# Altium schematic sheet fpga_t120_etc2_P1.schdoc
size 839 x 594 mm; Symbol: Drawing-Symbol_A4; @Project Name: FPGA_motors_V3_0_4; @Page Count: 1; @Update Date: 2025-12-23; @Create Date: 2025-12-23; @Schematic Name: fpga_t120_etc2; @Page No: 1; @Page Name: P1; Company: EasyEDA.com; Version: V1.0; Page Size: A4; @Create Time: 13:22:03; @Update Time: 14:22:09; Border: 1; Width: 3304; Height: 2338; Region Start: 1; X Region Count: 6; Y Region Count: 4; Blade Width: 10; Title Block Position: 3; Device: Drawing-Symbol_A4
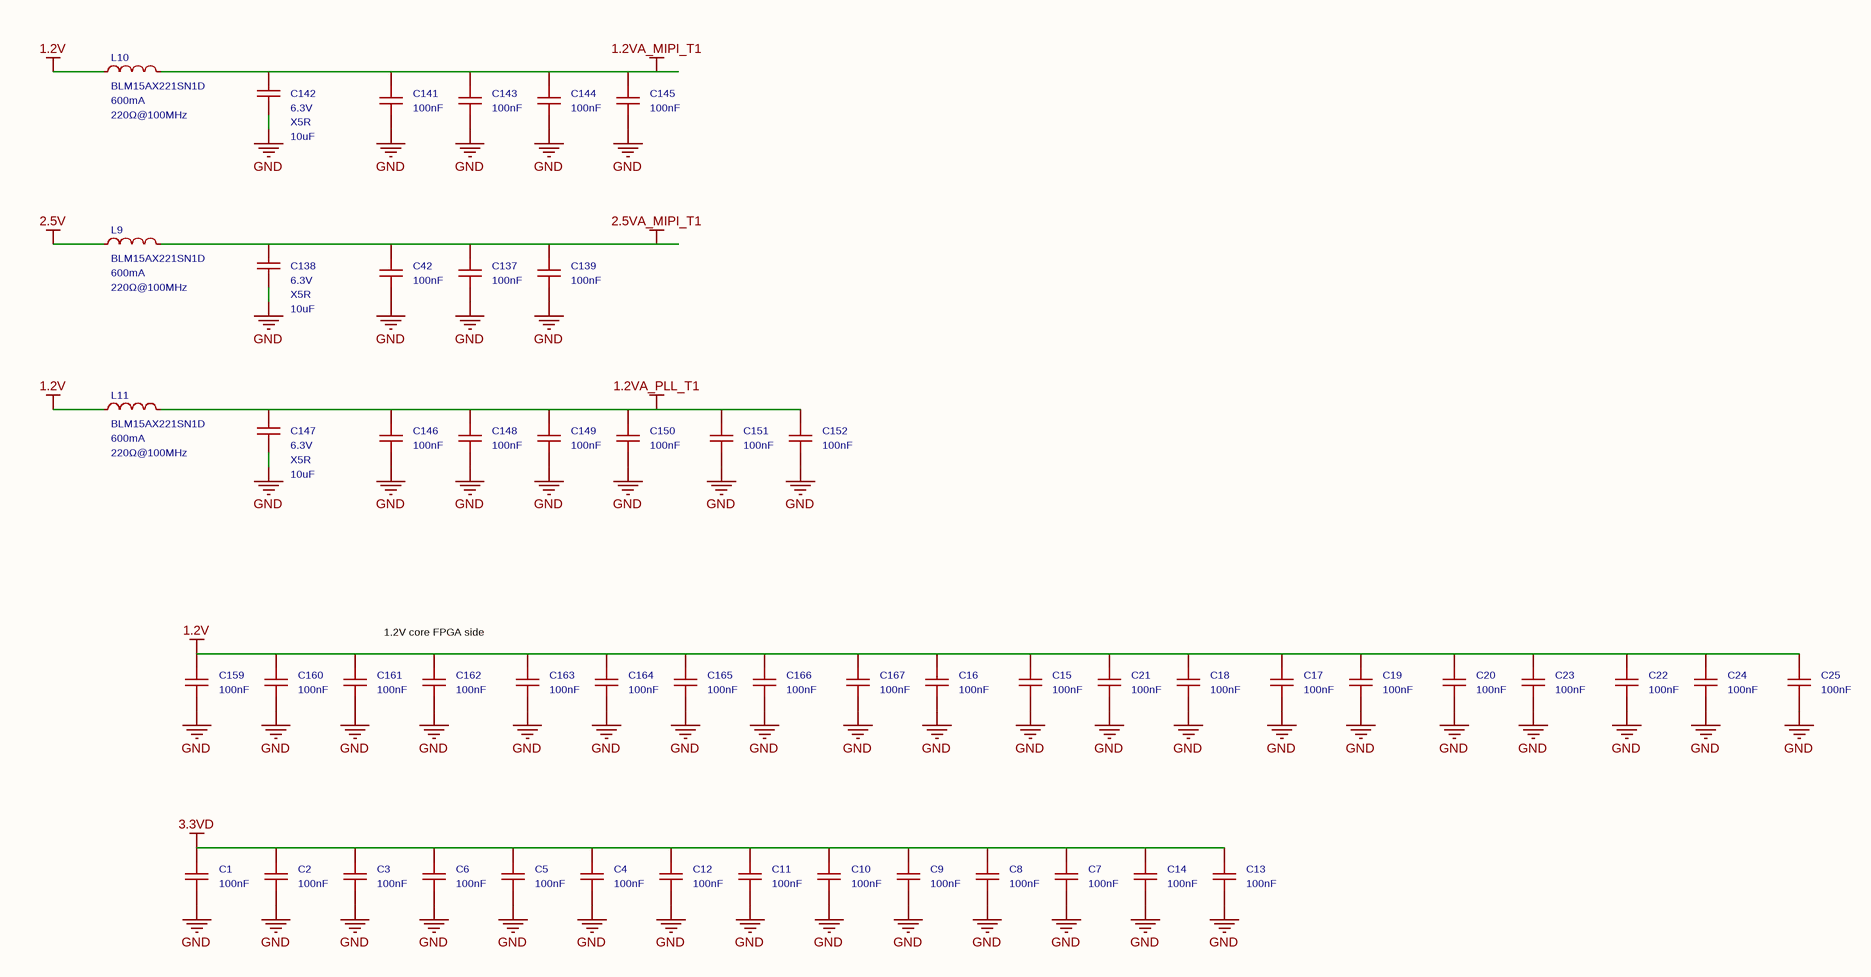
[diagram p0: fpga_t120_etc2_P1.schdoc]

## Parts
C1  100nF  [C0201]
C2  100nF  [C0201]
C3  100nF  [C0201]
C4  100nF  [C0201]
C5  100nF  [C0201]
C6  100nF  [C0201]
C7  100nF  [C0201]
C8  100nF  [C0201]
C9  100nF  [C0201]
C10  100nF  [C0201]
C11  100nF  [C0201]
C12  100nF  [C0201]
C13  100nF  [C0201]
C14  100nF  [C0201]
C15  100nF  [C0201]
C16  100nF  [C0201]
C17  100nF  [C0201]
C18  100nF  [C0201]
C19  100nF  [C0201]
C20  100nF  [C0201]
C21  100nF  [C0201]
C22  100nF  [C0201]
C23  100nF  [C0201]
C24  100nF  [C0201]
C25  100nF  [C0201]
C42  100nF  [C0201]
C137  100nF  [C0201]
C138  10uF  Voltage Rating: 6.3V  Temperature Coefficient: X5R  [C0402]
C139  100nF  [C0201]
C141  100nF  [C0201]
C142  10uF  Voltage Rating: 6.3V  Temperature Coefficient: X5R  [C0402]
C143  100nF  [C0201]
C144  100nF  [C0201]
C145  100nF  [C0201]
C146  100nF  [C0201]
C147  10uF  Voltage Rating: 6.3V  Temperature Coefficient: X5R  [C0402]
C148  100nF  [C0201]
C149  100nF  [C0201]
C150  100nF  [C0201]
C151  100nF  [C0201]
C152  100nF  [C0201]
C159  100nF  [C0201]
C160  100nF  [C0201]
C161  100nF  [C0201]
C162  100nF  [C0201]
C163  100nF  [C0201]
C164  100nF  [C0201]
C165  100nF  [C0201]
C166  100nF  [C0201]
C167  100nF  [C0201]
L9  BLM15AX221SN1D  Impedance @ Frequency: 220Ω@100MHz  Current Rating: 600mA  [L0402]
L10  BLM15AX221SN1D  Impedance @ Frequency: 220Ω@100MHz  Current Rating: 600mA  [L0402]
L11  BLM15AX221SN1D  Impedance @ Frequency: 220Ω@100MHz  Current Rating: 600mA  [L0402]

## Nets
1.2V: C15.1 C16.1 C17.1 C18.1 C19.1 C20.1 C21.1 C22.1 C23.1 C24.1 C25.1 C159.1 C160.1 C161.1 C162.1 C163.1 C164.1 C165.1 C166.1 C167.1 L10.1 L11.1
1.2VA_MIPI_T1: C141.1 C142.2 C143.1 C144.1 C145.1 L10.2
1.2VA_PLL_T1: C146.1 C147.2 C148.1 C149.1 C150.1 C151.1 C152.1 L11.2
2.5V: L9.1
2.5VA_MIPI_T1: C42.1 C137.1 C138.2 C139.1 L9.2
3.3VD: C1.2 C2.2 C3.2 C4.2 C5.2 C6.2 C7.2 C8.2 C9.2 C10.2 C11.2 C12.2 C13.2 C14.2
GND: C1.1 C2.1 C3.1 C4.1 C5.1 C6.1 C7.1 C8.1 C9.1 C10.1 C11.1 C12.1 C13.1 C14.1 C15.2 C16.2 C17.2 C18.2 C19.2 C20.2 C21.2 C22.2 C23.2 C24.2 C25.2 C42.2 C137.2 C138.1 C139.2 C141.2 C142.1 C143.2 C144.2 C145.2 C146.2 C147.1 C148.2 C149.2 C150.2 C151.2 C152.2 C159.2 C160.2 C161.2 C162.2 C163.2 C164.2 C165.2 C166.2 C167.2

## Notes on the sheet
- 1.2V core FPGA side

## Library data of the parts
C1-C14 = CL03A104KP3NNNC: Capacitance:100nF Tolerance:±10% Tolerance:±10% Voltage Rating:10V Temperature Coefficient:X5R; Manufacturer: SAMSUNG(三星); AddInBom: yes; ModelId: c3e75c3d90204c70b153866ab54c789f; ModelName: C0201_L0.6-W0.3-H0.3; ModelTransform: 23.622,11.811,0,0,0,0,0,0,0; Tolerance: ±10%; Voltage Rating: 10V; Temperature Coefficient: X5R
C15-C21 C42 C137 C139 C141 C143-C146 C148-C152 C159-C167 = CL03A104KP3NNNC: Capacitance:100nF Tolerance:±10% Tolerance:±10% Voltage Rating:10V Temperature Coefficient:X5R; Manufacturer: SAMSUNG(三星); Add into BOM: yes; 3D Model: c3e75c3d90204c70b153866ab54c789f; 3D Model Transform: 23.622,11.811,0,0,0,0,0,0,0; Tolerance: ±10%; Temperature Coefficient: X5R; Voltage Rating: 10V; ModelName: C0201_L0.6-W0.3-H0.3
C22-C25 = CL03A104KP3NNNC: Capacitance:100nF Tolerance:±10% Tolerance:±10% Voltage Rating:10V Temperature Coefficient:X5R; Manufacturer: SAMSUNG(三星); 3D Model: c3e75c3d90204c70b153866ab54c789f; 3D Model Transform: 23.622,11.811,0,0,0,0,0,0,0; Tolerance: ±10%; Temperature Coefficient: X5R; Add into BOM: yes; Voltage Rating: 10V; ModelName: C0201_L0.6-W0.3-H0.3
C138 C142 C147 = CL05A106MQ5NUNC: Capacitance:10uF Tolerance:±20% Tolerance:±20% Voltage Rating:6.3V Temperature Coefficient:X5R; Manufacturer: SAMSUNG(三星); AddInBom: yes; ModelId: b7d13df3e9464d7a99d0651d1a5b4d57; ModelName: C0402_L1.0-W0.5-H0.5; ModelTransform: 39.37,19.685,0,0,0,0,0,0,0; Tolerance: ±20%
L9-L11 = BLM15AX221SN1D: Impedance @ Frequency:220Ω@100MHz Tolerance:±25% Tolerance:±25% DC Resistance(DCR):180mΩ Current Rating:600mA Number of Circuits:1 Operating Temperature:-55℃~+125℃ Operating Temperature:-55℃~+125℃; Manufacturer: muRata(村田); AddInBom: yes; ModelId: aef00b1603224fd68a96e37121ccc916; ModelName: L0402_L1.0-W0.5-H0.5_BEAD; ModelTransform: 39.37,19.685,0,0,0,0,0,0.0005,0; Tolerance: ±25%; DC Resistance(DCR): 180mΩ; Number of Circuits: 1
